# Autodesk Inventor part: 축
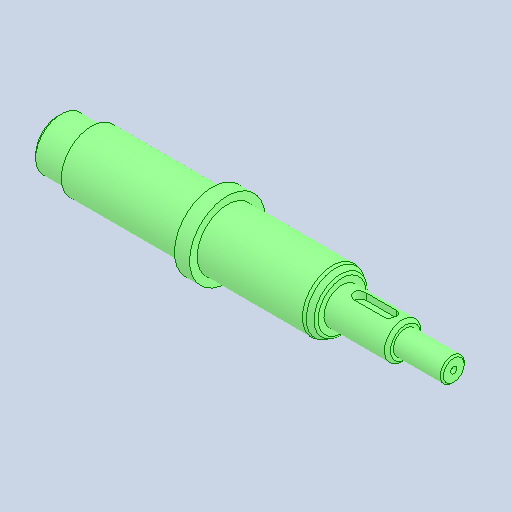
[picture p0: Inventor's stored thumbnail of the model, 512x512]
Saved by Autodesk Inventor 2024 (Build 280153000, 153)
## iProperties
Created: 2024-11
Part Number: 축
Material: 강철, 탄소
Document SubType Name: Modeling
Designer: user
Density: 7.85 g/cm^3
Appearance: 기본값
Author: jhkim
Sending System: Autodesk Inventor 2025
Preprocessor: ST-DEVELOPER v20
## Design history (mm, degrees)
node "축1"
node "솔리드2"
node "솔리드1"
